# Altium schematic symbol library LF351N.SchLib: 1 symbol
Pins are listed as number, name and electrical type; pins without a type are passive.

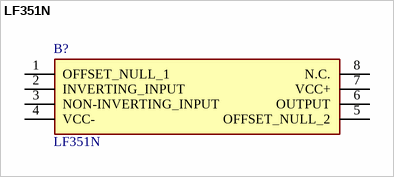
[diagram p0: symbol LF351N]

## LF351N
designator B?
IC OPAMP JFET 1 CIRCUIT 8DIP; Manufacturer_Name: STMicroelectronics; Geometry.Height: 5.33mm
footprint DIP762W56P254L959H533Q8N
pins: 1 OFFSET_NULL_1, 2 INVERTING_INPUT, 3 NON-INVERTING_INPUT, 4 VCC-, 5 OFFSET_NULL_2, 6 OUTPUT, 7 VCC+, 8 N.C.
